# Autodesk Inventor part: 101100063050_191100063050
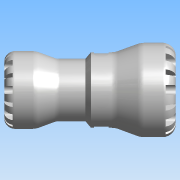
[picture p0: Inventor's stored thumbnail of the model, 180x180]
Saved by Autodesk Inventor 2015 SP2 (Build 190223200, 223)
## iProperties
Created: 2016-12
Part Number: 101100063050_191100063050
Material: PVC-Piping
Description: PLASSON REDUCING COUPLING 63X50 SERIES 1
Document SubType Name: Modeling
Designer: KIM
Mass: 113.204 g
Surface Area: 237.851 cm^2
Volume: 80.8599 cm^3
Density: 1.4 g/cm^3
Appearance: Smooth - White
Author: KIM
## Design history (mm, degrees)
derived "1011.ipt"
feature "Solid1::1011.ipt"
tag "TaggingFeature1"
body "Solid1"
other parameters: "d0" = 187, "d2" = 38.22, "d3" = 63, "d4" = 103, "d5" = 75.6, "d6" = 91, "d7" = 5.25, "d8" = 85, "d10" = 62.5, "d11" = 34.02, "d12" = 81, "d13" = 4.16667, "d14" = 82.4, "d15" = 68, "d16" = 20 deg, "d17" = 20 deg, "d18" = 130 deg, "d22" = 10.96, "d25" = 10.96, "d26" = 0, "d28" = 360 deg, "d30" = 8 deg, "d31" = 1.26, "d32" = 8 deg, "d33" = 1.26, "d35" = 0, "d37" = 360 deg, "d39" = 9, "d42" = 9, "d43" = 0, "d45" = 360 deg, "d47" = 1, "d48" = 8 deg, "d49" = 8 deg, "d50" = 1, "d52" = 0, "d54" = 360 deg, "d56" = 17, "d57" = 20.6, "d58" = 0.5, "d60" = 12.36, "d61" = 15.75, "d62" = 17.46, "d63" = 0, "d66" = 0, "d68" = 360 deg, "d75" = 11.03699, "d77" = 80.34, "d78" = 1.03, "d_" = 63, "E_" = 103, "H_" = 187, "l_" = 91, "E1" = 85, "l1" = 81, "Plasson" = 1, "d20" = 11.25, "d21" = 13.7, "d23" = 103, "d24" = 75.6, "d40" = 85, "d41" = 62.5, "d59" = 22.07398
